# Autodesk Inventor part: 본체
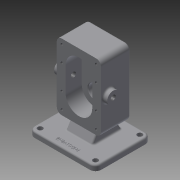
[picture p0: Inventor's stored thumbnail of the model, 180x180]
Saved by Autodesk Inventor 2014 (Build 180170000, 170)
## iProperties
Created: 2020-04
Part Number: 본체
Material: Generic
Document SubType Name: Modeling
Designer: kh
Density: 1 g/cm^3
Appearance: Default
Mass: 544.812 g
Surface Area: 819.925 cm^2
Volume: 544.812 cm^3
Author: kh
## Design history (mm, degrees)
sketch "스케치1"
  geometry: L1 (-50, 60)-(50, 60); L2 (50, 60)-(50, -60); L3 (50, -60)-(-50, -60); L4 (-50, -60)-(-50, 60); L5 (-50, 60)-(50, -60); L6 (50, 60)-(-50, -60); 3 further points
  constraints: 12 end point, 3 midpoint, 2 parallel, 1 coincident, 1 horizontal, 1 perpendicular
  dimensions: "d0" = 100 distance of L1.start L1.end; "d1" = 120 distance of L3.end L1.start
extrude "돌출1" new body sketch "스케치1" distance "d2" = 10; taper "d3" = 0 deg
node "작업 평면1"
sketch "스케치2"
  geometry: L1 (0, 0)-(0, 120) reference; L2 (0, 0)-(-10, 0) reference; L3 (-10, 120)-(-10, 0) reference; L4 (0, 120)-(-10, 120) reference; L5 (-150, 20)-(-30, 20); L6 (-30, 20)-(-30, 100); L7 (-30, 100)-(-150, 100); L8 (-150, 100)-(-150, 20); L9 (-150, 20)-(-30, 100); L10 (-30, 20)-(-150, 100); 4 further points
  constraints: 12 end point, 4 midpoint, 2 parallel, 1 horizontal, 1 horizontal alignment, 1 perpendicular
  dimensions: "d5" = 80 distance of L7.end L5.start; "d6" = 150 distance between parallel lines of L8 L1; "d7" = 120 distance between parallel lines of L6 L8
extrude "돌출2" join sketch "스케치2" distance "d8" = 53; taper "d9" = 0 deg
sketch "스케치3"
  geometry: L1 (30, 20)-(150, 20) reference; L2 (150, 20)-(150, 100) reference; L3 (150, 100)-(30, 100) reference; L4 (30, 100)-(30, 20) reference; L5 (0, 0)-(0, 120) reference; L6 (0, 0)-(10, 0) reference; L7 (10, 120)-(10, 0) reference; L8 (0, 120)-(10, 120) reference; L9 (68, 60)-(112, 60); L10 (68, 84)-(112, 84); L11 (112, 36)-(68, 36); A1 r 24 centre (68, 60) between (68, 84) and (68, 36); A2 r 24 centre (112, 60) between (112, 36) and (112, 84); 3 further points
  constraints: 8 end point, 4 point on circle, 4 tangent, 2 centre point, 2 midpoint, 2 parallel, 1 horizontal alignment
  dimensions: "d10" = 24 radius of A2; "d11" = 44 distance of L9.start L9.end; "d12" = 90 distance of point (90, 60) point (0, 60)
extrude "돌출3" cut sketch "스케치3" distance "d13" = 29; taper "d14" = 0 deg
sketch "스케치4"
  geometry: L1 (68, 84)-(112, 84) reference; L2 (112, 36)-(68, 36) reference; A1 r 24 centre (68, 60) between (68, 84) and (68, 36) reference; A2 r 24 centre (112, 60) between (112, 36) and (112, 84) reference; 3 further points
  constraints: 2 coincident
hole "구멍1" sketch "스케치4" at (112, 60), (68, 60) diameter "d15" = 25; stored, may be unused: countersink angle "d19" = 90 deg, drill point angle "d21" = 0 deg; dims "d16" = 6, "d17" = 4, "d18" = 2, "d20" = 15
sketch "스케치5"
  geometry: C1 r 12.5 at (-112, 60) reference; C2 r 19 at (-112, 60); 1 further point
  constraints: 1 centre point, 1 coincident
  dimensions: "d22" = 38 diameter of C2
extrude "돌출4" join sketch "스케치5" distance "d23" = 17; taper "d24" = 0 deg
hole "구멍2" diameter "d27" = 17; stored, may be unused: countersink angle "d31" = 90 deg, drill point angle "d33" = 0 deg; dims "d25" = 10, "d26" = 10, "d28" = 6, "d29" = 28, "d30" = 7.3, "d32" = 15
sketch "스케치6"
  geometry: L1 (17, -30)-(-83, -30) reference; L2 (-53, 0)-(-53, 120) reference; C1 r 11 at (-39, 60); 1 further point
  constraints: 1 centre point
  dimensions: "d34" = 22 diameter of C1; "d35" = 90 distance from line of L1 C1.centre; "d36" = 14 distance from line of L2 C1.centre
extrude "돌출5" join sketch "스케치6" distance "d37" = 8; taper "d38" = 0 deg
hole "구멍3" diameter "d41" = 8.917; stored, may be unused: countersink angle "d45" = 90 deg, drill point angle "d47" = 0 deg; dims "d39" = 10, "d40" = 10, "d42" = 6, "d43" = 28, "d44" = 7.3, "d46" = 15
sketch "스케치7"
  geometry: L1 (68, 84)-(112, 84) reference; L2 (112, 36)-(68, 36) reference; L3 (30, 20)-(150, 20) reference; L4 (150, 20)-(150, 100) reference; L5 (150, 100)-(30, 100) reference; L6 (30, 100)-(30, 20) reference; L7 (141, 91)-(39, 91); L8 (39, 91)-(39, 29); L9 (39, 29)-(141, 29); L10 (141, 29)-(141, 91); L11 (141, 91)-(39, 29); L12 (39, 91)-(141, 29); L13 (0, 0)-(0, 120) reference; L14 (112, 91)-(112, 29); L15 (68, 91)-(68, 29); A1 r 24 centre (68, 60) between (68, 84) and (68, 36) reference; A2 r 24 centre (112, 60) between (112, 36) and (112, 84) reference; 12 further points
  constraints: 16 end point, 8 coincident, 4 midpoint, 4 point on line, 3 perpendicular, 2 parallel, 1 horizontal, 1 horizontal alignment
  dimensions: "d48" = 62 distance of L9.end L7.start; "d49" = 90 distance from line of point (90, 60) L13; "d50" = 102 distance of L8.end L9.end; "d51" = 29 distance between parallel lines of L14 L10; "d52" = 44 distance from line of L15 L2.start
hole "구멍4" sketch "스케치7" at (141, 91), (112, 91), (68, 91), (39, 91), (39, 29), (68, 29), (112, 29), (141, 29) diameter "d53" = 4.459; stored, may be unused: countersink angle "d57" = 90 deg, drill point angle "d59" = 118 deg; dims "d54" = 10, "d55" = 28, "d56" = 7.3, "d58" = 12
sketch "스케치8"
  geometry: L1 (50, 10)-(50, 0) reference; L2 (50, 0)-(-50, 0) reference; L3 (-50, 0)-(-50, 10) reference; L4 (-50, 10)-(50, 10) reference; L5 (20, 30)-(-33, 30) reference; L6 (-33, 30)-(-33, 93) reference; L7 (-33, 93)-(-50, 93) reference; L8 (-50, 93)-(-50, 98) reference; L9 (-50, 98)-(-42.7, 98) reference; L10 (-42.7, 98)-(-42.7, 103.5) reference; L11 (-42.7, 103.5)-(-24, 103.5) reference; L12 (-24, 103.5)-(-24, 99.5) reference; L13 (-24, 99.5)-(-9, 99.5) reference; L14 (-9, 99.5)-(-9, 80.5) reference; L15 (-9, 80.5)-(-24, 80.5) reference; L16 (-24, 80.5)-(-24, 55.5) reference; L17 (-24, 55.5)-(-9, 55.5) reference; L18 (-9, 55.5)-(-9, 44) reference; L19 (-9, 44)-(20, 44) reference; L20 (20, 44)-(20, 30) reference; L21 (-33, 150)-(20, 150) reference; L22 (20, 150)-(20, 136) reference; L23 (20, 136)-(-9, 136) reference; L24 (-9, 136)-(-9, 124.5) reference; L25 (-9, 124.5)-(-24, 124.5) reference; L26 (-24, 124.5)-(-24, 120.5) reference; L27 (-24, 120.5)-(-42.7, 120.5) reference; L28 (-42.7, 120.5)-(-42.7, 126) reference; L29 (-42.7, 126)-(-50, 126) reference; L30 (-50, 126)-(-50, 131) reference; L31 (-50, 131)-(-33, 131) reference; L32 (-33, 131)-(-33, 150) reference; L33 (20, 10)-(8.453, 30); L34 (-33, 10)-(-21.453, 30); L35 (20, 10)-(-33, 10); L36 (8.453, 30)-(-21.453, 30); 1 further point
  constraints: 8 end point, 4 point on line, 2 collinear
  dimensions: "d60" = 17 distance from line of L3 L34.start; "d61" = 60 deg angle of L4 L34; "d62" = 53 distance of L33.start L34.start; "d63" = 60 deg angle of L4 L33
extrude "돌출6" join sketch "스케치8" stored distance "d64" = 48; taper "d65" = 0 deg
fillet "모깎기1" dims "d66" = 10
sketch "스케치9"
  geometry: L1 (40, 60)-(-40, 60) reference; L2 (-50, 50)-(-50, -50) reference; L3 (-40, -60)-(40, -60) reference; L4 (50, -50)-(50, 50) reference; L5 (33, -24)-(-20, -24) reference; L6 (-20, -24)-(-20, 24) reference; L7 (-20, 24)-(33, 24) reference; L8 (33, 24)-(33, -24) reference; A1 r 10 centre (40, 50) between (50, 50) and (40, 60) reference; A2 r 10 centre (-40, 50) between (-40, 60) and (-50, 50) reference; A3 r 10 centre (-40, -50) between (-50, -50) and (-40, -60) reference; A4 r 10 centre (40, -50) between (40, -60) and (50, -50) reference; 5 further points
  constraints: 4 coincident
hole "구멍5" sketch "스케치9" at (-40, 50), (-40, -50), (40, -50), (40, 50) diameter "d67" = 9; stored, may be unused: countersink angle "d71" = 90 deg, drill point angle "d73" = 118 deg; dims "d68" = 10, "d69" = 28, "d70" = 7.3, "d72" = 12
fillet "모깎기2" dims "d74" = 9
fillet "모깎기3" dims "d75" = 3
fillet "모깎기4" dims "d76" = 3
fillet "모깎기5" dims "d77" = 3
chamfer "모따기1" distance "d78" = 0.7; stored, may be unused: second distance "d79" = 2, angle "d80" = 30 deg
fillet "모깎기6" dims "d81" = 0.5
sketch "스케치10"
  geometry: L1 (-37.031, 20.509)-(-37.031, -20.97); L2 (-37.031, -20.97)-(-43.035, -20.97); L3 (-43.035, -20.97)-(-43.035, 20.509); L4 (-43.035, 20.509)-(-37.031, 20.509); L5 (-43.035, -20.97)-(-37.031, 20.509); L6 (-37.031, -20.059)-(-43.035, 20.509); L7 (-50, 50)-(-50, -50) reference; L8 (-40, -60)-(40, -60) reference; 2 further points
  constraints: 4 end point, 3 point on line, 2 other
  dimensions: "d82" = 10 distance from line of L7 point (-40, 0); "d83" = 60 distance from line of L8 point (-40, 0)
feature "엠보싱1" sketch "스케치10" dims "d0" = 100, "d1" = 120, "d84" = 0.5, "d85" = 0
chamfer "모따기2" distance "d86" = 1; stored, may be unused: second distance "d87" = 2, angle "d88" = 45 deg
node "솔리드1"
mirror "대칭1"
node "투영된 루프1"
node "투영된 루프2"
node "투영된 루프3"
node "투영된 루프4"
node "투영된 루프5"
node "투영된 루프6"
node "절단 모서리 투영1"
other parameters: "d4" = -17
